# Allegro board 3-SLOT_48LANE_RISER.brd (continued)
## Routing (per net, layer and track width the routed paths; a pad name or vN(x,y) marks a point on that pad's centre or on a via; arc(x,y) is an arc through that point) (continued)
PE_CPU_RX_DN<12>: length 12.1
  TOP w0.135: J5.A69 225.83,5.8 226.17,6.15 226.17,7.46 v2(225.83,7.8)
  IN2 w0.145: v2(225.83,7.8) 226.2,8.16 226.2,9.13 225.61,12.46 225.86,13.88 226.11,14.09 226.15,14.29 J1.A69
PE_CPU_RX_DN<13>: length 12.1
  TOP w0.135: v2(221.82,7.8) 222.17,7.45 222.17,6.15 221.83,5.8 J5.A73
  IN2 w0.145: J1.A73 222.15,14.29 222.11,14.09 221.86,13.88 221.61,12.46 222.2,9.13 222.2,8.17 221.83,7.8 v2(221.82,7.8)
PE_CPU_RX_DN<14>: length 12.1
  TOP w0.135: J5.A77 217.83,5.8 218.17,6.15 218.17,7.43 v2(217.81,7.8)
  IN2 w0.145: v2(217.81,7.8) 217.83,7.8 218.2,8.17 218.2,9.13 217.61,12.46 217.86,13.88 218.11,14.09 218.15,14.29 J1.A77
PE_CPU_RX_DN<15>: length 12.2
  TOP w0.135: J5.A81 213.83,5.52 214.2,5.89 214.2,6.26 214.45,7.28 214.45,7.43 v2(214.07,7.82)
  IN2 w0.145: v2(214.07,7.82) 214.13,7.83 214.42,8.24 213.64,12.64 213.86,13.88 214.11,14.09 214.15,14.29 J1.A81
PE_CPU_RX_DP<0>: length 12.2
  TOP w0.135: v2(278.84,7.8) 278.48,7.44 278.48,6.15 278.83,5.8 J5.A16
  IN2 w0.145: v2(278.84,7.8) 278.47,8.17 278.47,9.16 278.34,9.9 278.44,10.05 278.35,10.57 278.21,10.67 278.13,11.12 278.23,11.26 278.14,11.78 277.99,11.88 277.89,12.46 278.12,13.73 278.26,13.85 278.39,13.81 J1.A16
PE_CPU_RX_DP<1>: length 12.2
  TOP w0.135: v2(273.84,7.8) 273.48,7.44 273.48,6.15 273.83,5.8 J5.A21
  IN2 w0.145: v2(273.84,7.8) 273.46,8.18 274.13,11.99 273.97,12.92 273.97,12.94 273.96,12.95 273.8,13.86 273.61,14 273.58,14.01 273.54,14.03 273.48,14.24 J1.A21
PE_CPU_RX_DP<2>: length 12.2
  TOP w0.135: J5.A25 269.83,5.8 269.48,6.15 269.48,7.43 v2(269.85,7.8)
  IN2 w0.145: J1.A25 269.48,14.24 269.54,14.03 269.58,14.01 269.61,14 269.8,13.86 269.96,12.95 269.97,12.94 269.97,12.92 270.13,11.99 269.46,8.18 269.84,7.8 v2(269.85,7.8)
PE_CPU_RX_DP<3>: length 12.2
  TOP w0.135: v2(265.84,7.8) 265.48,7.44 265.48,6.15 265.83,5.81 J5.A29
  IN2 w0.145: J1.A29 265.48,14.24 265.54,14.03 265.58,14.01 265.61,14 265.8,13.86 265.96,12.95 265.97,12.94 265.97,12.92 266.13,11.99 265.46,8.18 v2(265.84,7.8)
PE_CPU_RX_DP<4>: length 12.2
  TOP w0.135: v2(259.84,7.8) 259.48,7.44 259.48,6.15 259.83,5.8 J5.A35
  IN2 w0.145: J1.A35 259.48,14.24 259.54,14.03 259.58,14.01 259.61,14 259.8,13.86 259.96,12.95 259.97,12.94 259.97,12.92 260.13,11.99 259.47,8.26 259.47,8.17 v2(259.84,7.8)
PE_CPU_RX_DP<5>: length 12.2
  TOP w0.135: v2(255.83,7.8) 255.48,7.45 255.48,6.15 255.83,5.8 J5.A39
  IN2 w0.145: v2(255.83,7.8) 255.46,8.17 255.46,8.18 256.13,11.99 255.97,12.92 255.97,12.94 255.96,12.95 255.8,13.86 255.61,14 255.58,14.01 255.54,14.03 255.48,14.24 J1.A39
PE_CPU_RX_DP<6>: length 12.2
  TOP w0.135: v2(251.84,7.8) 251.48,7.44 251.48,6.15 251.83,5.8 J5.A43
  IN2 w0.145: J1.A43 251.48,14.24 251.54,14.03 251.58,14.01 251.61,14 251.8,13.86 251.96,12.95 251.97,12.94 251.97,12.92 252.13,11.99 251.46,8.18 251.84,7.8 v2(251.84,7.8)
PE_CPU_RX_DP<7>: length 12.2
  TOP w0.135: v2(247.83,7.8) 247.48,7.45 247.48,6.15 247.83,5.8 J5.A47
  IN2 w0.145: v2(247.83,7.8) 247.47,8.16 247.47,8.26 248.13,11.99 247.97,12.92 247.97,12.94 247.96,12.95 247.8,13.86 247.61,14 247.58,14.01 247.54,14.03 247.48,14.24 J1.A47
PE_CPU_RX_DP<8>: length 12.2
  TOP w0.135: J5.A52 242.83,5.8 242.48,6.15 242.48,7.43 v2(242.85,7.8)
  IN2 w0.145: v2(242.85,7.8) 242.47,8.18 242.47,9.16 242.34,9.9 242.44,10.05 242.35,10.57 242.21,10.67 242.13,11.12 242.23,11.26 242.14,11.78 241.99,11.88 241.89,12.46 242.12,13.73 242.26,13.85 242.39,13.81 J1.A52
PE_CPU_RX_DP<9>: length 12.2
  TOP w0.135: v2(238.84,7.8) 238.48,7.44 238.48,6.15 238.83,5.8 J5.A56
  IN2 w0.145: J1.A56 238.39,13.81 238.26,13.85 238.12,13.73 237.89,12.46 237.99,11.88 238.14,11.78 238.23,11.26 238.13,11.12 238.21,10.67 238.35,10.57 238.44,10.05 238.34,9.9 238.47,9.16 238.47,8.17 v2(238.84,7.8)
PE_CPU_RX_DP<10>: length 12.2
  TOP w0.135: v2(234.82,7.8) 234.48,7.46 234.48,6.15 234.83,5.8 J5.A60
  IN2 w0.145: J1.A60 234.39,13.81 234.26,13.85 234.12,13.73 233.89,12.46 233.99,11.88 234.14,11.78 234.23,11.26 234.13,11.12 234.21,10.67 234.35,10.57 234.44,10.05 234.34,9.9 234.47,9.16 234.47,8.15 v2(234.82,7.8)
PE_CPU_RX_DP<11>: length 12.2
  TOP w0.135: J5.A64 230.83,5.8 230.48,6.15 230.48,7.44 v2(230.84,7.8)
  IN2 w0.145: v2(230.84,7.8) 230.47,8.16 230.47,9.16 230.34,9.9 230.44,10.05 230.35,10.57 230.21,10.67 230.13,11.12 230.23,11.26 230.14,11.78 229.99,11.88 229.89,12.46 230.12,13.73 230.26,13.85 230.39,13.81 J1.A64
PE_CPU_RX_DP<12>: length 12.2
  TOP w0.135: J5.A68 226.83,5.8 226.48,6.15 226.48,7.43 v2(226.85,7.8)
  IN2 w0.145: J1.A68 226.39,13.81 226.26,13.85 226.12,13.73 225.89,12.46 225.99,11.88 226.14,11.78 226.23,11.26 226.13,11.12 226.21,10.67 226.35,10.57 226.44,10.05 226.34,9.9 226.47,9.16 226.47,8.17 226.84,7.8 v2(226.85,7.8)
PE_CPU_RX_DP<13>: length 12.2
  TOP w0.135: J5.A72 222.83,5.8 222.48,6.15 222.48,7.45 v2(222.84,7.8)
  IN2 w0.145: J1.A72 222.39,13.81 222.26,13.85 222.12,13.73 221.89,12.46 221.99,11.88 222.14,11.78 222.23,11.26 222.13,11.12 222.21,10.67 222.35,10.57 222.44,10.05 222.34,9.9 222.47,9.16 222.47,8.16 v2(222.84,7.8)
PE_CPU_RX_DP<14>: length 12.2
  TOP w0.135: J5.A76 218.83,5.8 218.48,6.15 218.48,7.46 v2(218.82,7.8)
  IN2 w0.145: J1.A76 218.39,13.81 218.26,13.85 218.12,13.73 217.89,12.46 217.99,11.88 218.14,11.78 218.23,11.26 218.13,11.12 218.21,10.67 218.35,10.57 218.44,10.05 218.34,9.9 218.47,9.16 218.47,8.15 v2(218.82,7.8)
PE_CPU_RX_DP<15>: length 12.1
  TOP w0.135: v2(215.08,7.82) 214.76,7.5 214.76,7.24 214.5,6.22 214.5,5.89 214.83,5.57 J5.A80
  IN2 w0.145: J1.A80 214.39,13.81 214.26,13.85 214.12,13.73 213.92,12.64 214.7,8.25 214.77,8.04 v2(215.08,7.82)
PE_CPU_TX_DN<0>: length 16.9
  BOTTOM w0.135: J5.B15 279.83,5.8 280.17,6.15 280.17,6.81 279.93,8.2 279.64,8.61 279.36,9.02 279.2,9.91 279.33,10.64 279.21,10.8 279.3,11.33 279.47,11.44 279.69,12.7 279.69,13.5 280.65,14.47 280.65,15.96 280.5,16.11 280.5,16.52 280.65,16.67 280.65,18.03 280.51,18.17 280.38,18.24 280.2,18.18 J1.B15
PE_CPU_TX_DN<1>: length 16.9
  BOTTOM w0.135: J1.B20 275.2,18.69 275.14,18.52 274.94,18.42 274.67,18.15 274.67,14.43 275.7,13.4 275.7,12.28 275.34,10.22 275.55,9.03 275.17,6.92 275.17,6.15 274.83,5.8 J5.B20
PE_CPU_TX_DN<2>: length 16.9
  BOTTOM w0.135: J1.B24 271.2,18.69 271.14,18.51 271.11,18.49 270.91,18.39 270.67,18.15 270.67,14.35 271.65,13.37 271.65,12.27 271.47,11.2 271.35,10.56 271.59,9.19 271.17,6.8 271.17,6.15 270.83,5.8 J5.B24
PE_CPU_TX_DN<3>: length 16.9
  BOTTOM w0.135: J1.B28 267.2,18.69 267.14,18.52 266.94,18.42 266.67,18.15 266.67,14.43 267.64,13.46 267.64,12.37 267.32,10.56 267.55,9.25 267.17,7.1 267.17,6.15 266.83,5.8 J5.B28
PE_CPU_TX_DN<4>: length 16.9
  BOTTOM w0.135: J1.B34 261.2,18.69 261.14,18.51 260.92,18.4 260.68,18.16 260.68,14.25 261.68,13.25 261.68,12.34 261.52,11.39 261.34,10.37 261.56,9.13 261.17,6.96 261.17,6.15 260.83,5.8 J5.B34
PE_CPU_TX_DN<5>: length 16.8
  BOTTOM w0.135: J5.B38 256.83,5.8 257.17,6.15 257.17,6.8 257.39,8.05 257.4,8.05 257.55,8.94 257.3,10.37 257.49,11.44 257.66,12.39 257.66,13.34 256.7,14.29 256.7,18.18 256.92,18.4 257.14,18.51 257.2,18.69 J1.B38
PE_CPU_TX_DN<6>: length 16.8
  BOTTOM w0.135: J5.B42 252.83,5.8 253.17,6.15 253.17,7.22 253.52,9.2 253.3,10.48 253.64,12.43 253.64,13.4 252.7,14.34 252.7,18.18 252.92,18.4 253.14,18.51 253.2,18.69 J1.B42
PE_CPU_TX_DN<7>: length 16.8
  BOTTOM w0.135: J5.B46 248.83,5.8 249.17,6.15 249.17,7.35 249.52,9.32 249.31,10.52 249.64,12.4 249.64,13.44 248.7,14.38 248.7,18.18 248.92,18.4 249.14,18.51 249.2,18.69 J1.B46
PE_CPU_TX_DN<8>: length 16.8
  BOTTOM w0.135: J5.B51 243.83,5.8 244.17,6.15 244.17,6.95 243.75,9.35 243.98,10.62 243.84,11.36 243.67,11.48 243.6,11.88 243.72,12.06 243.65,12.46 243.65,13.42 244.67,14.43 244.67,16.08 244.51,16.24 244.51,16.64 244.67,16.79 244.67,18.01 244.51,18.17 244.38,18.24 244.2,18.18 J1.B51
PE_CPU_TX_DN<9>: length 16.7
  BOTTOM w0.135: J5.B55 239.83,5.8 240.17,6.15 240.17,7.04 239.8,9.17 240.04,10.51 239.88,11.39 239.7,11.51 239.63,11.91 239.76,12.09 239.69,12.48 239.69,13.59 240.63,14.53 240.63,15.98 240.48,16.14 240.48,16.54 240.63,16.69 240.63,18.05 240.51,18.17 240.38,18.24 240.2,18.18 J1.B55
PE_CPU_TX_DN<10>: length 16.7
  BOTTOM w0.135: J1.B59 236.2,18.18 236.38,18.24 236.51,18.17 236.65,18.03 236.65,16.86 236.5,16.71 236.5,16.3 236.65,16.15 236.65,14.33 235.71,13.39 235.71,12.48 235.79,12.05 235.66,11.88 235.74,11.43 235.92,11.31 236.09,10.35 235.83,8.85 236.17,6.88 236.17,6.15 235.83,5.8 J5.B59
PE_CPU_TX_DN<11>: length 16.7
  BOTTOM w0.135: J1.B63 232.2,18.18 232.38,18.24 232.51,18.17 232.67,18.02 232.67,16.87 232.51,16.72 232.51,16.31 232.67,16.16 232.67,14.61 231.69,13.64 231.69,12.45 231.78,11.97 231.65,11.79 231.72,11.39 231.9,11.27 232.07,10.32 231.85,9.08 232.17,7.22 232.17,6.15 231.83,5.8 J5.B63
PE_CPU_TX_DN<12>: length 16.9
  BOTTOM w0.135: J5.B67 227.83,5.8 228.17,6.15 228.17,7.72 228.05,8.43 227.87,8.56 227.8,8.96 227.93,9.13 227.86,9.53 228.01,10.41 227.86,11.3 227.68,11.42 227.61,11.82 227.73,12 227.69,12.25 227.69,13.61 228.68,14.61 228.68,16.11 228.52,16.26 228.52,16.67 228.68,16.82 228.68,18.03 228.55,18.15 228.38,18.24 228.2,18.18 J1.B67
PE_CPU_TX_DN<13>: length 16.9
  BOTTOM w0.135: J1.B71 224.2,18.18 224.38,18.24 224.51,18.17 224.67,18.01 224.67,16.74 224.52,16.59 224.52,16.19 224.67,16.03 224.67,14.58 223.68,13.59 223.68,12.47 223.75,12.09 223.62,11.91 223.7,11.51 223.87,11.39 224.04,10.41 223.83,9.22 223.9,8.82 223.78,8.65 223.85,8.25 224.03,8.12 224.17,7.29 224.17,6.15 223.83,5.8 J5.B71
PE_CPU_TX_DN<14>: length 16.8
  BOTTOM w0.135: J1.B75 220.2,18.18 220.38,18.24 220.51,18.17 220.68,18 220.68,16.92 220.53,16.77 220.53,16.37 220.68,16.21 220.68,14.45 219.67,13.44 219.67,11.68 219.57,11.53 219.64,11.13 219.81,11 219.93,10.37 219.72,9.24 220.17,6.69 220.17,6.15 219.83,5.8 J5.B75
PE_CPU_TX_DN<15>: length 17
  BOTTOM w0.135: J1.B79 216.2,18.18 216.38,18.24 216.51,18.17 216.69,17.99 216.69,16.9 216.54,16.75 216.54,16.35 216.69,16.19 216.69,14.48 215.67,13.46 215.67,12.24 215.81,11.83 215.72,11.63 215.84,11.25 216.04,11.15 216.32,10.32 216.24,9.9 216.07,9.78 216,9.38 216.12,9.2 216.09,9.02 216.17,8.54 216.17,5.89 215.83,5.54 J5.B79
PE_CPU_TX_DP<0>: length 17
  BOTTOM w0.135: J5.B14 280.83,5.8 280.48,6.15 280.48,6.83 280.22,8.32 279.64,9.14 279.51,9.9 279.99,12.67 279.99,13.38 280.96,14.34 280.96,18.15 280.69,18.43 280.52,18.51 280.46,18.69 J1.B14
PE_CPU_TX_DP<1>: length 16.9
  BOTTOM w0.135: J1.B19 275.46,18.18 275.27,18.24 275.12,18.17 274.98,18.03 274.98,16.74 275.13,16.58 275.13,16.18 274.98,16.03 274.98,14.56 276.01,13.53 276.01,12.25 275.92,11.74 276.04,11.57 275.97,11.17 275.79,11.05 275.65,10.22 275.86,9.03 275.77,8.56 275.9,8.39 275.83,7.99 275.65,7.86 275.48,6.89 275.48,6.15 275.83,5.8 J5.B19
PE_CPU_TX_DP<2>: length 16.8
  BOTTOM w0.135: J5.B23 271.83,5.8 271.48,6.15 271.48,6.78 271.9,9.19 271.66,10.56 271.77,11.14 271.94,11.27 272.01,11.67 271.89,11.84 271.96,12.24 271.96,13.49 270.98,14.47 270.98,16.03 271.13,16.18 271.13,16.58 270.98,16.74 270.98,18.03 271.09,18.14 271.28,18.24 271.46,18.18 J1.B23
PE_CPU_TX_DP<3>: length 16.9
  BOTTOM w0.135: J5.B27 267.83,5.8 267.48,6.15 267.48,7.07 267.67,8.15 267.85,8.27 267.92,8.67 267.79,8.85 267.86,9.25 267.63,10.56 267.75,11.25 267.93,11.37 268,11.77 267.88,11.95 267.95,12.34 267.95,13.59 266.98,14.56 266.98,16.03 267.13,16.18 267.13,16.58 266.98,16.74 266.98,18.03 267.12,18.17 267.27,18.24 267.46,18.18 J1.B27
PE_CPU_TX_DP<4>: length 16.9
  BOTTOM w0.135: J5.B33 261.83,5.8 261.48,6.15 261.48,6.94 261.67,8.03 261.85,8.15 261.92,8.55 261.8,8.73 261.87,9.13 261.65,10.37 261.79,11.21 261.97,11.34 262.04,11.73 261.92,11.91 261.99,12.31 261.99,13.38 260.98,14.38 260.98,16.05 261.14,16.21 261.14,16.61 260.98,16.76 260.98,18.03 261.11,18.15 261.28,18.24 261.46,18.18 J1.B33
PE_CPU_TX_DP<5>: length 16.7
  BOTTOM w0.135: J5.B37 257.83,5.8 257.48,6.15 257.48,6.77 257.67,7.84 257.67,7.84 257.86,8.94 257.61,10.37 257.77,11.26 257.95,11.39 258.02,11.78 257.89,11.96 257.96,12.36 257.96,13.46 257.01,14.42 257.01,16 257.16,16.15 257.16,16.55 257.01,16.71 257.01,18.06 257.11,18.15 257.28,18.24 257.46,18.18 J1.B37
PE_CPU_TX_DP<6>: length 16.9
  BOTTOM w0.135: J5.B41 253.83,5.8 253.48,6.15 253.48,7.19 253.64,8.11 253.82,8.23 253.89,8.63 253.76,8.8 253.83,9.2 253.61,10.48 253.76,11.31 253.93,11.43 254,11.83 253.88,12 253.95,12.4 253.95,13.53 253.01,14.47 253.01,16 253.16,16.15 253.16,16.55 253.01,16.71 253.01,18.06 253.11,18.15 253.28,18.24 253.46,18.18 J1.B41
PE_CPU_TX_DP<7>: length 16.9
  BOTTOM w0.135: J1.B45 249.46,18.18 249.28,18.24 249.11,18.15 249.01,18.06 249.01,16.71 249.16,16.55 249.16,16.15 249.01,16 249.01,14.51 249.95,13.57 249.95,12.38 249.88,11.98 250,11.8 249.93,11.4 249.75,11.28 249.62,10.52 249.83,9.32 249.76,8.92 249.89,8.75 249.82,8.35 249.64,8.23 249.48,7.32 249.48,6.15 249.83,5.8 J5.B45
PE_CPU_TX_DP<8>: length 16.9
  BOTTOM w0.135: J5.B50 244.83,5.8 244.48,6.15 244.48,6.98 244.06,9.35 244.28,10.62 243.96,12.48 243.96,13.29 244.97,14.31 244.97,18.14 244.69,18.43 244.52,18.51 244.46,18.69 J1.B50
PE_CPU_TX_DP<9>: length 16.8
  BOTTOM w0.135: J1.B54 240.46,18.69 240.52,18.51 240.69,18.43 240.93,18.18 240.93,14.41 239.99,13.47 239.99,12.51 240.35,10.51 240.11,9.17 240.48,7.06 240.48,6.15 240.83,5.8 J5.B54
PE_CPU_TX_DP<10>: length 16.8
  BOTTOM w0.135: J1.B58 236.46,18.69 236.52,18.51 236.52,18.51 236.69,18.43 236.96,18.15 236.96,14.2 236.02,13.26 236.02,12.51 236.15,11.76 236.21,11.41 236.4,10.35 236.14,8.85 236.48,6.91 236.48,6.15 236.83,5.8 J5.B58
PE_CPU_TX_DP<11>: length 16.8
  BOTTOM w0.135: J5.B62 232.83,5.8 232.48,6.15 232.48,7.25 232.16,9.08 232.38,10.32 232.2,11.32 232.2,11.32 232.2,11.32 232,12.48 232,13.51 232.97,14.48 232.97,18.14 232.69,18.43 232.52,18.51 232.52,18.51 232.46,18.69 J1.B62
PE_CPU_TX_DP<12>: length 16.9
  BOTTOM w0.135: J1.B66 228.46,18.69 228.52,18.51 228.73,18.4 228.98,18.15 228.98,14.48 227.99,13.49 227.99,12.28 228.32,10.42 228.16,9.53 228.47,7.77 228.48,7.77 228.48,6.15 228.83,5.8 J5.B66
PE_CPU_TX_DP<13>: length 16.9
  BOTTOM w0.135: J1.B70 224.46,18.69 224.52,18.51 224.69,18.43 224.98,18.13 224.98,14.46 223.99,13.47 223.99,12.5 224.35,10.41 224.14,9.22 224.48,7.32 224.48,6.15 224.83,5.8 J5.B70
PE_CPU_TX_DP<14>: length 16.9
  BOTTOM w0.135: J5.B74 220.83,5.8 220.48,6.15 220.48,6.72 220.03,9.24 220.23,10.37 219.98,11.84 219.98,13.31 220.98,14.32 220.98,18.13 220.69,18.43 220.52,18.51 220.46,18.69 J1.B74
PE_CPU_TX_DP<15>: length 16.9
  BOTTOM w0.135: J1.B78 216.46,18.69 216.52,18.51 216.69,18.43 216.99,18.12 216.99,14.35 215.98,13.34 215.98,12.29 216.63,10.34 216.4,9.02 216.48,8.56 216.48,5.9 216.83,5.55 J5.B78
PE_SLOT2_PRES_N: length 166.6
  TOP w0.114: R44.2 59.89,63.6 61.14,62.36 92.46,62.36 v2(101.07,53.75) ; J2.B81 213.83,37.94 212.79,38.97 212.5,38.97 209.91,41.57 209.91,41.74 209.79,41.86 168.28,41.86 v2(158.73,51.41)
  IN2 w0.147: v2(101.07,53.75) 103.18,55.85 153.83,55.85 158.28,51.41 v2(158.73,51.41)
PE_SLOT2_RX_DN<0>: length 229.5
  IN2 w0.089: 74.39,75.64 74.37,75.64 74.33,75.68 73.54,75.68 73.12,75.27 73.12,75.19 73.12,75.12 72.85,74.84 72.77,74.84 72.7,74.84 72.4,74.55 72.01,74.55 71.93,74.47 71.48,74.47 71.4,74.55 69.84,74.55 v3(69.65,74.36)
  IN2 w0.145: J2.A17 278.2,34.51 278.4,34.44 278.54,34.52 278.69,34.67 278.69,38.11 277.65,39.15 277.65,40.65 277.34,41.09 277.34,41.09 276.05,42.93 275.75,44.63 274.73,46.09 272.3,47.79 272.1,47.76 271.54,48.16 271.5,48.35 271.03,48.68 270.87,48.65 270.26,49.08 270.23,49.24 269.76,49.57 269.54,49.53 269,49.91 268.96,50.13 255.75,59.38 184.1,72.01 180.82,74.31 137.84,81.89 96.66,74.63 95.12,74.9 94.98,74.8 94.48,74.89 94.38,75.03 93.94,75.11 93.8,75.01 93.29,75.1 93.2,75.24 92.75,75.31 92.61,75.22 92.11,75.31 92.01,75.44 90.72,75.67 89.74,75.5 89.65,75.38 89.11,75.28 88.99,75.37 88.55,75.29 88.46,75.17 87.92,75.07 87.8,75.16 86.95,75.01 85.91,75.01 85.78,74.88 85.3,74.88 85.17,75.01 84.72,75.01 84.59,74.88 84.11,74.88 83.98,75.01 82.97,75.01 82.17,75.15 82.02,75.04 81.54,75.13 81.44,75.28 81,75.35 80.85,75.25 80.37,75.34 80.27,75.48 79.39,75.64 76.84,75.64 76.71,75.51 76.23,75.51 76.1,75.64 75.65,75.64 75.52,75.51 75.04,75.51 74.91,75.64 74.39,75.64
  BOTTOM w0.135: U1.D11 v3(69.65,74.36)
PE_SLOT2_RX_DN<1>: length 228.4
  IN2 w0.089: v3(69.65,73.56) 69.84,73.75 69.98,73.75 70.18,73.95 70.89,73.95 71.17,73.67 74.38,73.67 74.43,73.63 74.45,73.63
  IN2 w0.145: 74.45,73.63 74.8,73.63 75.14,73.69 75.53,73.85 75.69,73.78 76.18,73.99 76.24,74.15 76.66,74.32 76.82,74.25 77.31,74.46 77.37,74.62 77.62,74.72 78.05,74.79 79.96,74.46 80.12,74.24 80.09,74.08 80.38,73.67 80.87,73.58 81.28,73.87 81.31,74.02 81.53,74.18 82.98,73.92 84.15,73.92 84.26,73.81 84.89,73.81 85,73.92 85.45,73.92 85.56,73.81 86.19,73.81 86.3,73.92 87.3,73.92 90.63,74.51 96.77,73.43 118.26,77.22 118.27,77.22 137.86,80.67 180.43,73.17 183.78,70.83 254.02,58.45 260.51,53.91 260.54,53.7 261.09,53.32 261.29,53.36 261.77,53.02 261.8,52.83 262.35,52.44 262.55,52.48 263.02,52.14 263.05,51.98 263.64,51.57 263.81,51.6 264.28,51.26 264.31,51.08 264.89,50.68 265.06,50.71 267.79,48.81 267.84,48.54 267.22,47.66 267.31,47.17 267.72,46.88 268.21,46.97 268.83,47.85 269.09,47.89 270.38,47 271.83,44.92 272.33,42.08 273.69,40.14 273.69,39.33 272.69,38.33 272.69,34.55 272.95,34.29 273.14,34.2 273.15,34.18 273.21,34.02 J2.A22
  BOTTOM w0.135: U1.D10 v3(69.65,73.56)
PE_SLOT2_RX_DN<2>: length 220.5
  IN2 w0.089: v3(69.65,71.96) 69.84,72.15 74.38,72.15 74.43,72.1 74.45,72.1
  IN2 w0.145: J2.A26 269.21,34.02 269.15,34.18 269.14,34.2 268.95,34.29 268.69,34.55 268.69,38.27 269.67,39.26 269.67,40.67 267.71,43.47 267.44,45 266.92,45.74 266.74,45.77 266.33,46.37 266.36,46.54 266.02,47.02 265.88,47.04 265.44,47.67 265.46,47.82 264.93,48.58 251.99,57.64 183.47,69.72 179.91,72.21 137.99,79.6 96.6,72.3 90.85,73.32 87.15,72.67 86.31,72.67 86.18,72.54 85.69,72.54 85.56,72.67 85.11,72.67 84.98,72.54 84.49,72.54 84.36,72.67 83.91,72.67 83.78,72.54 83.3,72.54 83.17,72.67 82.72,72.67 82.59,72.54 82.1,72.54 81.97,72.67 81.52,72.67 81.39,72.54 80.9,72.54 80.77,72.67 80.32,72.67 80.19,72.54 79.7,72.54 79.58,72.67 78.13,72.67 74.94,72.1 74.45,72.1
  BOTTOM w0.135: U1.D8 v3(69.65,71.96)
PE_SLOT2_RX_DN<3>: length 220.1
  IN2 w0.089: v3(69.65,71.16) 69.84,71.35 69.98,71.35 70.18,71.55 71.96,71.55 73.88,71.21 74.38,71.21 74.43,71.17 74.45,71.17
  IN2 w0.145: 74.45,71.17 75.3,71.17 78.28,71.69 78.87,71.69 78.99,71.57 79.58,71.57 79.7,71.69 80.15,71.69 80.27,71.57 80.86,71.57 80.98,71.69 81.43,71.69 81.55,71.57 82.14,71.57 82.27,71.69 83.87,71.69 84,71.56 84.57,71.56 84.7,71.69 85.15,71.69 85.28,71.56 85.86,71.56 85.98,71.69 87.61,71.69 90.96,72.28 92.58,72 92.65,71.89 93.22,71.79 93.32,71.87 93.76,71.79 93.83,71.69 94.4,71.59 94.5,71.66 96.52,71.3 137.7,78.56 179.08,71.27 182.83,68.64 240.86,58.42 250.66,56.69 255.02,53.63 255.07,53.38 255.45,53.11 255.7,53.16 256.09,52.89 256.14,52.63 256.52,52.36 256.77,52.41 258.65,51.09 259.2,50.31 259.15,50.04 258.26,49.42 258.17,48.93 258.46,48.51 258.96,48.43 259.85,49.05 260.11,49 260.27,48.78 260.22,48.52 259.69,48.14 259.61,47.71 259.96,47.23 260.39,47.15 260.92,47.52 261.18,47.48 262.56,45.51 262.56,45.5 263.15,42.2 263.44,41.78 263.7,40.31 263.7,39.13 264.69,38.15 264.69,34.55 264.95,34.29 265.14,34.2 265.15,34.18 265.21,34.02 J2.A30
  BOTTOM w0.135: U1.D7 v3(69.65,71.16)
PE_SLOT2_RX_DN<4>: length 211
  IN2 w0.089: v3(69.65,69.56) 69.84,69.75 72.04,69.75 72.87,69.89 74.04,69.89 74.08,69.85 74.1,69.85
  IN2 w0.145: J2.A36 259.21,34.02 259.15,34.18 259.14,34.2 258.95,34.29 258.69,34.55 258.69,38.35 259.69,39.36 259.69,40.31 259.61,40.77 258.43,42.46 258.19,42.7 257.61,43.52 257.23,45.7 256.09,47.31 255.9,47.35 255.59,47.79 255.62,47.98 255.34,48.38 255.17,48.41 254.84,48.88 254.87,49.05 254.6,49.45 254.44,49.48 254.1,49.97 254.13,50.12 253.85,50.52 253.67,50.55 253.35,51.02 253.38,51.19 252.08,53.04 247.9,55.97 236.18,58.03 182.4,67.52 178.49,70.25 137.66,77.45 95.84,70.08 90.46,71.03 87.19,70.45 82.78,70.45 82.69,70.36 82.11,70.36 82.02,70.45 81.57,70.45 81.48,70.36 80.9,70.36 80.81,70.45 80.37,70.45 80.27,70.36 79.7,70.36 79.61,70.45 78.07,70.45 77.33,70.32 77.24,70.19 76.66,70.09 76.53,70.18 76.08,70.1 75.99,69.97 75.41,69.86 75.28,69.96 74.68,69.85 74.1,69.85
  BOTTOM w0.135: U1.D5 v3(69.65,69.56)
PE_SLOT2_RX_DN<5>: length 209.2
  IN2 w0.089: 73.84,68.83 73.82,68.83 73.77,68.87 73.3,68.87 73.02,69.15 72.66,69.15 72.6,69.09 72.08,69.09 72.01,69.15 71.62,69.15 71.56,69.09 71.04,69.09 70.97,69.15 70.18,69.15 69.98,68.95 69.84,68.95 v3(69.65,68.76)
  IN2 w0.145: 73.84,68.83 74.99,68.83 75.77,68.97 75.91,68.87 76.49,68.97 76.59,69.11 77.03,69.19 77.17,69.09 77.76,69.2 77.85,69.33 78.26,69.41 87.77,69.41 87.9,69.28 88.6,69.28 88.73,69.41 89.73,69.41 90.09,69.66 90.13,69.9 90.35,70.06 90.62,70.01 90.78,69.79 90.73,69.54 91.02,69.13 91.52,69.04 91.93,69.33 91.97,69.58 92.19,69.73 92.46,69.68 92.61,69.46 92.57,69.21 92.86,68.8 93.49,68.69 93.49,68.69 137.24,76.4 177.86,69.24 181.77,66.5 245.04,55.35 245.98,54.69 246.02,54.48 246.43,54.19 246.64,54.23 247.05,53.94 247.09,53.74 247.5,53.45 247.71,53.48 249.54,52.2 251.07,50.01 251.05,49.85 251.38,49.37 251.54,49.35 251.99,48.7 251.96,48.54 252.28,48.08 252.45,48.05 253,47.26 253.76,42.95 254.83,41.41 255.59,40.62 255.68,40.12 255.68,39.36 254.69,38.37 254.69,34.55 254.95,34.29 255.14,34.2 255.15,34.18 255.21,34.02 J2.A40
  BOTTOM w0.135: U1.D4 v3(69.65,68.76)
PE_SLOT2_RX_DN<6>: length 202.6
  IN2 w0.089: v3(69.65,67.16) 69.84,67.35 69.98,67.35 70.18,67.55 70.89,67.55 71.17,67.27 72.22,67.27 72.26,67.23 72.29,67.23
  IN2 w0.145: J2.A44 251.21,34.02 251.15,34.18 251.14,34.2 250.95,34.29 250.69,34.55 250.69,38.33 251.66,39.31 251.66,39.95 251.55,40.58 251.02,41.34 250.05,42.73 249.6,45.31 249.17,45.92 249.04,45.94 248.68,46.45 248.7,46.59 248.42,46.99 248.27,47.01 247.92,47.5 247.95,47.66 247.67,48.06 247.5,48.09 247.17,48.56 247.2,48.73 246.92,49.13 246.76,49.15 246.43,49.64 246.45,49.8 245.78,50.76 245.64,50.78 245.34,51.22 245.36,51.36 244.94,51.95 240.69,54.93 228.55,57.07 181.41,65.38 177.38,68.21 136.97,75.33 93.29,67.63 92.21,67.83 92.07,67.73 91.53,67.82 91.43,67.96 90.99,68.04 90.85,67.94 90.3,68.04 90.21,68.18 89.43,68.32 85.08,68.32 84.96,68.2 84.36,68.2 84.24,68.32 80.59,68.32 80.46,68.19 79.97,68.19 79.84,68.32 78.76,68.32 74.45,67.56 72.59,67.23 72.29,67.23
  BOTTOM w0.135: U1.D2 v3(69.65,67.16)
PE_SLOT2_RX_DN<7>: length 200.6
  IN2 w0.089: 71.93,66.5 71.91,66.5 71.86,66.55 71.07,66.55 70.98,66.46 70.54,66.46 70.46,66.55 69.84,66.55 v3(69.65,66.36)
  IN2 w0.145: J2.A48 247.21,34.02 247.15,34.18 247.14,34.2 246.95,34.29 246.69,34.55 246.69,38.11 245.7,39.1 245.7,40.92 245.62,41.34 245.05,42.15 244.87,42.19 244.59,42.59 244.62,42.77 244.36,43.14 244.18,43.17 243.9,43.58 243.93,43.76 243.25,44.73 242.93,46.54 242.86,46.59 242.74,47.27 242.79,47.34 242.7,47.83 242.59,47.91 242.48,48.51 242.56,48.62 242.47,49.11 242.35,49.2 242.25,49.79 242.33,49.91 242.15,50.94 241.53,51.83 240.04,52.87 239.94,52.85 239.3,53.3 239.29,53.4 238,54.3 237.08,54.46 237.02,54.42 235.9,54.61 235.86,54.67 181,64.35 177.26,66.96 136.72,74.11 90.31,65.93 89.32,66.1 89.03,66.51 89.13,67.04 88.97,67.26 88.7,67.3 88.48,67.15 88.39,66.63 87.98,66.34 86.64,66.58 86.35,66.99 86.4,67.25 86.28,67.42 85.93,67.48 85.76,67.36 85.71,67.1 85.3,66.81 84.46,66.96 84.28,66.83 83.83,66.91 83.71,67.09 82.83,67.25 81.6,67.25 81.36,67 80.47,67 80.22,67.25 79.65,67.25 79.4,67 78.52,67 78.27,67.25 77.68,67.25 75.79,66.91 75.67,66.75 75.2,66.66 75.04,66.77 73.58,66.51 73.56,66.5 71.93,66.5
  BOTTOM w0.135: U1.D1 v3(69.65,66.36)
PE_SLOT2_RX_DN<8>: length 197.3
  IN2 w0.089: v3(66.45,68.76) 66.64,68.58 66.64,67.08 66.59,67.04 66.54,66.99 66.54,66.6 66.59,66.55 66.64,66.5 66.64,65.95 66.59,65.91 66.59,65.89
  IN2 w0.145: 66.59,65.89 66.59,65.42 66.99,65.02 70.81,65.02 71.42,65.63 74.21,65.63 74.45,65.68 76.16,65.98 76.84,65.98 76.98,65.85 77.48,65.85 77.61,65.98 78.06,65.98 78.19,65.85 78.7,65.85 78.83,65.98 79.28,65.98 79.41,65.85 79.92,65.85 80.05,65.98 80.5,65.98 80.63,65.85 81.14,65.85 81.27,65.98 83.32,65.98 83.92,65.87 84.02,65.73 84.55,65.64 84.7,65.74 85.14,65.66 85.24,65.51 85.77,65.42 85.91,65.52 86.36,65.44 86.46,65.3 86.99,65.21 87.13,65.31 90.24,64.76 136.7,72.95 176.99,65.85 180.69,63.25 225.22,55.4 237.56,46.76 239.16,44.47 239.13,44.3 239.42,43.89 239.59,43.86 239.85,43.49 239.82,43.32 240.11,42.91 240.28,42.88 241.69,40.87 241.69,39.25 242.67,38.26 242.67,34.65 242.54,34.52 242.4,34.44 242.2,34.51 J2.A53
  BOTTOM w0.135: U1.H4 v3(66.45,68.76)
PE_SLOT2_RX_DN<9>: length 196
  IN2 w0.089: 65.64,67.08 65.66,67.1 65.72,67.1 66.08,67.46 66.08,68.13 65.84,68.38 65.84,68.58 v3(65.65,68.76)
  IN2 w0.145: J2.A57 238.2,34.51 238.4,34.44 238.54,34.52 238.69,34.67 238.69,38.26 237.71,39.24 237.71,40.47 236.57,42.23 236.4,42.26 236.11,42.7 236.15,42.87 235.9,43.25 235.74,43.28 235.45,43.72 235.49,43.89 235.17,44.38 233.46,46.82 231.04,49.24 223.35,54.63 179.95,62.28 176.18,64.92 136.42,71.93 89.77,63.71 88.77,63.88 88.63,63.78 88.13,63.87 88.04,64.01 87.59,64.09 87.45,63.99 86.95,64.08 86.85,64.22 86.41,64.3 86.27,64.2 85.77,64.29 85.67,64.43 85.23,64.51 85.09,64.41 84.59,64.5 84.49,64.64 83.18,64.87 82.67,64.87 82.55,64.75 81.97,64.75 81.86,64.87 81.34,64.87 81.02,64.54 80.17,64.54 79.84,64.87 79.23,64.87 78.9,64.54 78.06,64.54 77.73,64.87 77.12,64.87 76.79,64.54 75.94,64.54 75.62,64.87 74.87,64.87 74.73,64.73 74.2,64.73 74.05,64.87 72.84,64.87 72.2,64.24 66.51,64.24 66.17,64.58 66.02,64.58 65.62,64.98 65.62,65.13 65.32,65.43 65.32,65.72 65.22,65.83 65.22,66.39 65.32,66.5 65.32,66.76 65.64,67.08
  BOTTOM w0.135: U1.J4 v3(65.65,68.76)
PE_SLOT2_RX_DN<10>: length 194.2
  IN2 w0.089: 63.62,65.84 63.62,65.86 63.66,65.91 63.66,66.65 64.24,67.23 64.24,68.58 v3(64.05,68.76)
  IN2 w0.145: 63.62,65.84 63.62,64.88 63.98,64.52 63.98,64.32 64.34,63.96 64.54,63.96 65.03,63.47 73.54,63.47 74.1,62.92 75.31,62.92 75.86,63.47 76.62,63.47 77.17,62.92 78.09,62.92 78.56,63.39 79.44,63.39 79.56,63.26 80.06,63.26 80.19,63.39 80.64,63.39 80.76,63.26 81.26,63.26 81.39,63.39 82.13,63.39 82.24,63.27 82.79,63.27 82.91,63.39 84.56,63.39 85.45,63.11 85.54,62.94 86.01,62.79 86.17,62.88 86.6,62.74 86.69,62.58 87.15,62.43 87.32,62.52 88.07,62.28 136.49,70.82 175.8,63.89 179.24,61.48 221.13,54.09 224.96,51.41 225,51.2 225.37,50.94 225.58,50.98 225.94,50.72 225.98,50.51 226.35,50.25 226.56,50.29 227.6,49.56 230.48,45.45 230.48,45.45 231.16,44.47 231.13,44.31 231.43,43.89 231.59,43.86 233.61,40.97 233.73,40.29 233.73,39.25 234.7,38.29 234.7,34.68 234.54,34.52 234.4,34.44 234.2,34.51 J2.A61
  BOTTOM w0.135: U1.L4 v3(64.05,68.76)
PE_SLOT2_RX_DN<11>: length 193.1
  IN2 w0.089: v3(63.25,68.76) 63.44,68.58 63.44,68.38 63.72,68.1 63.72,67.8 62.84,66.92 62.84,66.01 62.79,65.96 62.79,65.94
  IN2 w0.145: 62.79,65.94 62.79,64.02 63.55,63.26 63.55,63 63.85,62.71 63.85,62.52 64.21,62.16 64.39,62.16 64.71,61.85 64.71,61.66 65.07,61.3 65.25,61.3 65.72,60.83 66.9,60.83 67.04,60.69 67.54,60.69 67.68,60.83 69.59,60.83 69.72,60.7 70.2,60.7 70.33,60.83 70.78,60.83 70.91,60.7 71.39,60.7 71.52,60.83 74.61,60.83 74.74,60.7 75.23,60.7 75.36,60.83 75.81,60.83 75.94,60.7 76.43,60.7 76.56,60.83 77.41,60.83 77.81,61.24 78.43,61.24 78.83,60.83 79.88,60.83 80.38,60.92 80.58,61.21 81.23,61.32 81.52,61.12 82.31,61.26 82.51,61.55 83.15,61.67 83.44,61.46 84.28,61.61 85.8,61.34 85.81,61.34 86.86,61.15 133.85,69.44 134.01,69.32 134.51,69.41 134.62,69.57 136.27,69.87 175.44,62.97 178.83,60.6 219.43,53.44 222.19,51.68 225.62,46.79 225.59,46.63 225.9,46.19 226.06,46.16 226.32,45.79 226.29,45.63 226.6,45.18 226.76,45.16 229.47,41.29 229.69,40.04 229.69,39.23 230.68,38.24 230.68,34.66 230.54,34.52 230.4,34.44 230.2,34.51 J2.A65
  BOTTOM w0.135: U1.M4 v3(63.25,68.76)
PE_SLOT2_RX_DN<12>: length 191.8
  IN2 w0.089: 61.23,66.43 61.23,66.45 61.28,66.5 61.28,67 61.04,67.24 61.04,68.58 v3(60.85,68.76)
  IN2 w0.145: 61.23,66.43 61.23,65.96 61.14,65.86 61.04,65.76 61.04,65.31 61.14,65.21 61.23,65.11 61.23,64.56 61.84,63.96 61.84,62.3 62.51,61.63 62.51,61.45 62.89,61.07 63.07,61.07 64.47,59.67 64.47,59.5 64.85,59.12 65.03,59.12 65.49,58.65 76.51,58.65 77.41,58.81 78.16,59.33 84.19,60.4 86.37,60.01 136.27,68.8 155.78,65.36 175.28,61.92 178.73,59.51 209.23,54.13 209.32,54 209.81,53.91 209.94,54.01 210.34,53.94 210.43,53.81 210.92,53.72 211.05,53.81 211.87,53.67 212.7,53.52 212.79,53.39 213.29,53.3 213.42,53.39 213.81,53.32 213.9,53.19 214.39,53.11 214.53,53.2 215.35,53.05 218.17,52.56 220.01,51.27 221.41,49.26 221.38,49.12 221.71,48.65 221.86,48.63 222.42,47.83 222.39,47.66 222.66,47.28 222.82,47.25 223.05,46.92 223.02,46.76 223.29,46.37 223.46,46.34 224.01,45.55 224.17,44.62 224.11,44.53 224.24,43.79 224.33,43.72 224.5,42.75 225.54,41.27 225.69,40.42 225.69,39.23 226.68,38.24 226.68,34.66 226.54,34.52 226.4,34.44 226.2,34.51 J2.A69
  BOTTOM w0.135: U1.P4 v3(60.85,68.76)
PE_SLOT2_RX_DN<13>: length 189.7
  IN2 w0.089: v3(60.05,68.76) 60.24,68.58 60.24,66.8 60.19,66.76 60.19,66.73
  IN2 w0.145: J2.A73 222.2,34.51 222.4,34.44 222.54,34.52 222.68,34.66 222.68,38.06 222.53,38.35 222.08,38.73 221.78,39.03 221.69,39.52 221.69,40.23 221.43,41.68 220.4,43.16 220.16,44.51 220.05,44.59 219.92,45.31 220,45.42 219.9,45.99 219.82,46.05 219.68,46.82 219.74,46.9 219.46,48.48 217.66,51.06 217,51.51 215.22,51.83 215.09,51.74 214.6,51.82 214.51,51.95 214.11,52.02 213.98,51.93 213.49,52.02 213.4,52.15 211.82,52.43 205.03,53.62 204.21,53.77 204.08,53.68 203.59,53.76 203.5,53.9 203.1,53.96 202.97,53.87 202.48,53.96 202.39,54.09 201.56,54.24 178.21,58.36 174.35,61.05 137.13,67.62 136.68,67.7 86.06,58.77 83.73,59.18 83.15,59.08 83.05,58.94 82.55,58.85 82.41,58.95 81.35,58.76 81.26,58.63 80.7,58.53 80.59,58.61 78.5,58.24 77.74,57.93 76.77,57.76 64.99,57.76 62.66,60.08 62.49,60.08 62.11,60.46 62.11,60.64 60.19,62.55 60.19,63.52 60.04,63.67 60.04,64.2 60.19,64.35 60.19,64.79 60.06,64.93 60.06,65.46 60.19,65.59 60.19,66.73
  BOTTOM w0.135: U1.R4 v3(60.05,68.76)
PE_SLOT2_RX_DN<14>: length 188.4
  IN2 w0.089: 58.52,66.56 58.52,66.59 58.56,66.62 58.56,66.83 57.86,67.53 57.86,68.2 58.08,68.42 58.08,68.99 v3(58.45,69.56)
  IN2 w0.145: 58.52,66.56 58.52,62.34 63.99,56.87 72.46,56.87 72.9,56.43 73.51,56.43 73.95,56.87 79.09,56.87 79.54,57.32 79.9,57.32 80.36,56.87 81.23,56.87 84.46,57.44 84.69,57.78 85.12,57.85 85.56,57.54 135.07,66.32 135.22,66.22 135.8,66.32 135.9,66.47 136.85,66.64 173.31,60.21 173.34,60.2 173.37,60.19 173.82,60.11 178.14,57.1 211.59,51.13 214.13,49.35 215.14,47.91 215.12,47.78 215.51,47.22 215.64,47.19 216.35,46.18 216.5,45.35 216.24,43.84 216.46,42.55 217.58,40.95 217.68,40.41 217.68,39.48 218.16,38.79 218.41,38.62 218.54,38.43 218.68,37.64 218.68,34.66 218.54,34.52 218.4,34.44 218.2,34.51 J2.A77
  BOTTOM w0.135: v3(58.45,69.56) 58.85,69.96 U1.U5
PE_SLOT2_RX_DN<15>: length 186.2
  IN2 w0.089: 57.37,66.14 57.37,66.17 57.42,66.21 57.42,66.9 57.28,67.04 57.28,68.99 v3(57.65,69.56)
  IN2 w0.145: J2.A81 214.2,34.51 214.4,34.44 214.54,34.52 214.68,34.66 214.68,38.06 213.79,39.33 213.67,40.03 213.67,40.72 212.84,45.41 210.65,48.54 209.84,49.11 209.68,49.08 209.29,49.35 209.26,49.51 208.59,49.98 208.43,49.95 208.04,50.22 208.02,50.38 207.47,50.77 177.62,56.03 172.96,59.29 137.57,65.54 86.75,56.51 86.11,56.62 81.23,55.76 80.95,55.48 76.79,54.74 71.42,54.74 70.94,55.22 70.61,55.22 70.13,54.74 69.56,54.74 69.08,55.22 68.74,55.22 68.26,54.74 67.69,54.74 67.21,55.22 66.88,55.22 66.4,54.74 64.42,54.74 57.37,61.78 57.37,66.14
  BOTTOM w0.135: v3(57.65,69.56) 58.05,69.96 U1.V5
PE_SLOT2_RX_DP<0>: length 229.5
  IN2 w0.089: 74.39,75.92 74.37,75.92 74.33,75.87 73.46,75.87 72.33,74.74 69.39,74.74 v3(68.85,74.36)
  IN2 w0.145: J2.A16 278.46,34 278.52,34.2 278.7,34.29 278.97,34.55 278.97,38.23 277.93,39.27 277.93,40.74 277.57,41.25 276.31,43.04 276.01,44.74 274.93,46.29 255.86,59.64 184.21,72.27 180.93,74.57 137.84,82.17 96.66,74.91 90.72,75.96 86.92,75.29 83,75.29 79.41,75.92 74.39,75.92
  BOTTOM w0.135: U1.E11 v3(68.85,74.36)
PE_SLOT2_RX_DP<1>: length 228.5
  IN2 w0.089: v3(68.85,73.56) 69.39,73.94 69.9,73.94 70.11,74.14 70.97,74.14 71.25,73.86 74.38,73.86 74.43,73.91 74.45,73.91
  IN2 w0.145: 74.45,73.91 74.77,73.91 75.05,73.96 77.54,74.99 78.05,75.08 80.13,74.71 80.41,74.3 80.39,74.15 80.54,73.92 80.81,73.88 81.03,74.03 81.06,74.19 81.47,74.48 83.01,74.2 87.28,74.2 90.63,74.79 96.77,73.71 118.22,77.49 118.22,77.5 137.86,80.96 180.54,73.43 183.89,71.09 254.13,58.71 268.04,48.97 268.13,48.48 267.51,47.6 267.56,47.33 267.78,47.17 268.05,47.22 268.67,48.1 269.16,48.19 270.58,47.2 272.09,45.03 272.59,42.19 273.97,40.23 273.97,39.22 272.97,38.22 272.97,34.67 273.12,34.52 273.26,34.44 273.46,34.51 J2.A21
  BOTTOM w0.135: U1.E10 v3(68.85,73.56)
PE_SLOT2_RX_DP<2>: length 220.6
  IN2 w0.089: v3(68.85,71.96) 69.39,72.34 74.38,72.34 74.43,72.38 74.45,72.38
  IN2 w0.145: J2.A25 269.46,34.51 269.26,34.44 269.26,34.45 269.12,34.52 268.97,34.67 268.97,38.15 269.95,39.14 269.95,40.76 267.97,43.58 267.7,45.11 265.13,48.78 252.1,57.9 183.58,69.99 180.02,72.48 137.99,79.89 96.6,72.59 90.85,73.6 87.13,72.95 78.11,72.95 74.92,72.38 74.45,72.38
  BOTTOM w0.135: U1.E8 v3(68.85,71.96)
PE_SLOT2_RX_DP<3>: length 220.1
  IN2 w0.089: v3(68.85,71.16) 69.39,71.54 69.9,71.54 70.11,71.74 71.99,71.74 71.99,71.74 73.9,71.4 74.38,71.4 74.43,71.45 74.45,71.45
  IN2 w0.145: 74.45,71.45 75.28,71.45 78.25,71.97 87.59,71.97 90.96,72.57 96.52,71.59 137.7,78.85 179.19,71.53 182.94,68.91 240.97,58.68 250.77,56.95 258.85,51.29 259.49,50.38 259.41,49.88 258.52,49.26 258.47,48.99 258.62,48.77 258.89,48.72 259.78,49.35 260.28,49.26 260.56,48.85 260.48,48.35 259.95,47.98 259.91,47.78 260.12,47.48 260.32,47.45 260.85,47.82 261.35,47.73 262.1,46.65 262.82,45.63 262.84,45.57 263.41,42.31 263.7,41.89 263.98,40.34 263.98,39.25 264.97,38.26 264.97,34.67 265.12,34.52 265.26,34.44 265.46,34.51 J2.A29
  BOTTOM w0.135: U1.E7 v3(68.85,71.16)
PE_SLOT2_RX_DP<4>: length 211.2
  IN2 w0.089: v3(68.85,69.56) 69.39,69.94 72.03,69.94 72.86,70.08 74.04,70.08 74.08,70.13 74.1,70.13
  IN2 w0.145: 74.1,70.13 74.65,70.13 78.05,70.73 87.16,70.73 90.46,71.31 95.84,70.36 137.66,77.74 178.6,70.52 182.51,67.79 236.29,58.3 248.01,56.23 252.28,53.24 257.49,45.81 257.87,43.63 258.4,42.88 258.64,42.64 259.88,40.88 259.88,40.88 259.97,40.33 259.97,39.24 258.97,38.24 258.97,34.67 259.12,34.52 259.26,34.44 259.46,34.51 J2.A35
  BOTTOM w0.135: U1.E5 v3(68.85,69.56)
PE_SLOT2_RX_DP<5>: length 209.4
  IN2 w0.089: v3(68.85,68.76) 69.39,69.14 69.9,69.14 70.11,69.34 73.1,69.34 73.38,69.06 73.77,69.06 73.82,69.11 73.84,69.11
  IN2 w0.145: J2.A39 255.46,34.51 255.26,34.44 255.12,34.52 254.97,34.67 254.97,38.25 255.96,39.24 255.96,40.15 255.85,40.76 255.05,41.59 254.03,43.05 253.27,47.37 249.74,52.4 245.15,55.62 181.88,66.77 177.97,69.51 137.24,76.69 93.5,68.97 93.02,69.06 92.87,69.28 92.91,69.53 92.62,69.94 92.13,70.03 91.72,69.74 91.67,69.49 91.45,69.34 91.18,69.38 91.03,69.6 91.07,69.85 90.79,70.26 90.29,70.35 89.88,70.06 89.84,69.82 89.65,69.68 78.24,69.68 74.96,69.11 73.84,69.11
  BOTTOM w0.135: U1.E4 v3(68.85,68.76)
PE_SLOT2_RX_DP<6>: length 202.7
  IN2 w0.089: v3(68.85,67.16) 69.39,67.54 69.9,67.54 70.11,67.74 70.97,67.74 71.25,67.46 72.22,67.46 72.26,67.51 72.29,67.51
  IN2 w0.145: 72.29,67.51 72.56,67.51 74.45,67.84 78.73,68.6 89.45,68.6 93.29,67.92 136.97,75.62 177.49,68.48 181.52,65.65 228.66,57.34 240.8,55.2 245.15,52.15 249.86,45.42 250.32,42.84 251.82,40.69 251.94,39.97 251.94,39.19 250.97,38.21 250.97,34.67 251.12,34.52 251.26,34.44 251.46,34.51 J2.A43
  BOTTOM w0.135: U1.E2 v3(68.85,67.16)
PE_SLOT2_RX_DP<7>: length 200.7
  IN2 w0.089: v3(68.85,66.36) 69.39,66.74 71.86,66.74 71.91,66.78 71.93,66.78
  IN2 w0.145: 71.93,66.78 73.52,66.78 73.55,66.79 74.45,66.95 77.66,67.53 78.39,67.53 78.63,67.28 79.29,67.28 79.53,67.53 80.34,67.53 80.59,67.28 81.24,67.28 81.49,67.53 82.86,67.53 85.23,67.11 85.46,67.26 85.5,67.53 85.86,67.78 86.45,67.67 86.7,67.31 86.65,67.05 86.81,66.83 87.91,66.63 88.13,66.79 88.23,67.31 88.64,67.6 89.13,67.51 89.42,67.1 89.33,66.58 89.48,66.36 90.31,66.21 136.72,74.4 177.37,67.23 181.11,64.61 238.11,54.56 241.73,52.03 242.42,51.05 243.51,44.84 245.89,41.45 245.98,40.94 245.98,39.22 246.97,38.23 246.97,34.67 247.12,34.52 247.26,34.44 247.46,34.51 J2.A47
  BOTTOM w0.135: U1.E1 v3(68.85,66.36)
PE_SLOT2_RX_DP<8>: length 197.4
  IN2 w0.089: 66.87,65.89 66.87,65.91 66.83,65.95 66.83,68.99 v3(66.45,69.56)
  IN2 w0.145: 66.87,65.89 66.87,65.54 67.11,65.3 70.69,65.3 71.3,65.91 74.18,65.91 74.45,65.96 76.14,66.26 83.35,66.26 90.24,65.04 136.7,73.23 177.1,66.11 180.8,63.52 225.33,55.67 237.76,46.96 241.97,40.95 241.97,39.36 242.95,38.38 242.95,34.54 242.7,34.29 242.52,34.2 242.46,34 J2.A52
  BOTTOM w0.135: U1.H5 v3(66.45,69.56)
PE_SLOT2_RX_DP<9>: length 196.1
  IN2 w0.089: 65.84,66.89 65.85,66.9 65.85,66.97 66.27,67.38 66.27,68.21 66.03,68.45 66.03,68.99 v3(65.65,69.56)
  IN2 w0.145: 65.84,66.89 65.6,66.65 65.6,65.54 66.63,64.52 72.09,64.52 72.72,65.15 75.73,65.15 76.06,64.82 76.67,64.82 77,65.15 77.85,65.15 78.17,64.82 78.79,64.82 79.11,65.15 79.96,65.15 80.29,64.82 80.9,64.82 81.23,65.15 83.2,65.15 89.77,63.99 136.42,72.22 176.29,65.19 180.06,62.55 223.46,54.89 231.22,49.46 233.68,47 235.41,44.53 237.99,40.55 237.99,39.36 238.97,38.38 238.97,34.55 238.7,34.29 238.52,34.2 238.51,34.19 238.45,34.01 J2.A56
  BOTTOM w0.135: U1.J5 v3(65.65,69.56)
PE_SLOT2_RX_DP<10>: length 194.3
  IN2 w0.089: 63.9,65.84 63.9,65.86 63.85,65.91 63.85,66.57 64.43,67.15 64.43,68.99 v3(64.05,69.56)
  IN2 w0.145: J2.A60 234.49,33.94 234.58,34.23 234.7,34.29 234.98,34.56 234.98,38.4 234.01,39.37 234.01,40.31 233.88,41.08 227.8,49.76 221.24,54.36 179.34,61.74 175.91,64.15 136.49,71.1 88.09,62.57 84.6,63.67 78.44,63.67 77.97,63.2 77.29,63.2 76.73,63.75 75.75,63.75 75.19,63.2 74.21,63.2 73.66,63.75 65.14,63.75 63.9,65 63.9,65.84
  BOTTOM w0.135: U1.L5 v3(64.05,69.56)
PE_SLOT2_RX_DP<11>: length 193.2
  IN2 w0.089: v3(63.25,69.56) 63.63,68.99 63.63,68.45 63.91,68.17 63.91,67.72 63.03,66.84 63.03,66.01 63.07,65.96 63.07,65.94
  IN2 w0.145: 63.07,65.94 63.07,64.13 63.83,63.37 63.83,63.12 65.84,61.11 77.29,61.11 77.7,61.52 78.54,61.52 78.94,61.11 79.86,61.11 80.22,61.18 80.42,61.47 81.29,61.62 81.58,61.42 82.15,61.52 82.35,61.81 83.22,61.96 83.51,61.76 84.28,61.89 85.85,61.61 86.86,61.44 136.27,70.15 175.55,63.24 178.94,60.87 219.53,53.71 222.39,51.89 229.74,41.4 229.97,40.06 229.97,39.35 230.96,38.35 230.96,34.55 230.7,34.29 230.51,34.19 230.45,34.01 J2.A64
  BOTTOM w0.135: U1.M5 62.85,69.96 v3(63.25,69.56)
PE_SLOT2_RX_DP<12>: length 191.8
  IN2 w0.089: v3(60.85,69.56) 61.23,68.99 61.23,67.32 61.47,67.08 61.47,66.5 61.51,66.45 61.51,66.43
  IN2 w0.145: J2.A68 226.46,34 226.52,34.2 226.7,34.29 226.96,34.55 226.96,38.35 225.97,39.35 225.97,40.44 225.8,41.38 224.77,42.86 224.27,45.66 220.21,51.47 218.28,52.82 178.84,59.77 175.39,62.19 136.27,69.09 86.37,60.3 84.19,60.68 78.06,59.6 77.3,59.07 76.48,58.93 65.61,58.93 62.12,62.42 62.12,64.07 61.51,64.67 61.51,66.43
  BOTTOM w0.135: U1.P5 v3(60.85,69.56)
PE_SLOT2_RX_DP<13>: length 189.8
  IN2 w0.089: v3(60.05,69.56) 60.43,68.99 60.43,66.8 60.47,66.76 60.47,66.73
  IN2 w0.145: J2.A72 222.46,34 222.52,34.2 222.7,34.29 222.96,34.55 222.96,38.13 222.75,38.53 222.26,38.94 222.04,39.16 221.97,39.55 221.97,40.26 221.7,41.79 220.66,43.27 219.72,48.59 217.86,51.26 217.11,51.78 178.32,58.62 174.46,61.32 137.18,67.89 136.68,67.98 87.13,59.24 86.06,59.05 83.73,59.47 78.49,58.54 77.66,58.2 76.75,58.04 65.1,58.04 60.47,62.67 60.47,66.73
  BOTTOM w0.135: v3(60.05,69.56) 60.45,69.96 U1.R5
PE_SLOT2_RX_DP<14>: length 188.3
  IN2 w0.089: 58.8,66.56 58.8,66.59 58.75,66.64 58.75,66.91 58.05,67.61 58.05,68.12 58.27,68.34 58.27,68.58 v3(58.45,68.76)
  IN2 w0.145: J2.A76 218.46,34 218.52,34.2 218.7,34.29 218.96,34.55 218.96,37.67 218.81,38.54 218.61,38.82 218.36,38.99 217.96,39.57 217.96,40.43 217.85,41.06 216.73,42.66 216.62,43.25 216.52,43.84 216.78,45.35 216.62,46.29 214.34,49.55 211.7,51.4 178.25,57.36 173.93,60.38 173.45,60.46 173.38,60.48 173.36,60.48 136.85,66.92 85.63,57.84 85.19,58.15 84.53,58.03 84.3,57.7 81.2,57.15 80.47,57.15 80.02,57.6 79.42,57.6 78.97,57.15 73.83,57.15 73.39,56.71 73.01,56.71 72.58,57.15 64.11,57.15 62.74,58.52 62.74,58.7 62.27,59.17 62.09,59.17 61.8,59.46 61.8,59.68 61.37,60.11 61.15,60.11 60.89,60.36 60.89,60.56 60.44,61.02 60.24,61.02 59.82,61.43 59.82,61.62 59.35,62.09 59.17,62.09 58.8,62.46 58.8,63.64 58.92,63.76 58.92,64.27 58.8,64.39 58.8,64.84 58.92,64.96 58.92,65.47 58.8,65.59 58.8,66.56
  BOTTOM w0.135: U1.U4 v3(58.45,68.76)
PE_SLOT2_RX_DP<15>: length 186.1
  IN2 w0.089: v3(57.65,68.76) 57.47,68.58 57.47,67.12 57.61,66.98 57.61,66.21 57.65,66.17 57.65,66.14
  IN2 w0.145: 57.65,66.14 57.65,61.9 58.08,61.47 58.25,61.47 58.62,61.1 58.62,60.93 58.99,60.56 59.16,60.56 59.53,60.2 59.53,60.03 60.06,59.49 60.23,59.49 60.6,59.12 60.6,58.96 60.97,58.58 61.14,58.58 61.51,58.22 61.51,58.05 61.91,57.64 62.08,57.64 62.45,57.27 62.45,57.11 62.82,56.73 62.99,56.73 63.35,56.37 63.35,56.2 64.53,55.02 66.28,55.02 66.76,55.5 67.33,55.5 67.81,55.02 68.15,55.02 68.63,55.5 69.19,55.5 69.67,55.02 70.01,55.02 70.49,55.5 71.06,55.5 71.54,55.02 76.76,55.02 80.81,55.74 81.1,56.02 86.11,56.91 86.75,56.79 137.57,65.82 173.07,59.56 177.73,56.3 207.58,51.03 210.84,48.75 213.1,45.52 213.95,40.74 213.95,40.06 214.05,39.44 214.96,38.14 214.96,34.55 214.7,34.29 214.52,34.2 214.46,34 J2.A80
  BOTTOM w0.135: U1.V4 v3(57.65,68.76)
PE_SLOT2_TX_C_DN<0>: length 219.1
  BOTTOM w0.135: U1.A11 71.75,74.67 72.48,74.67 72.62,74.8 73.07,74.8 73.2,74.67 73.76,74.67 74.2,75.11 78.34,75.11 78.56,74.88 79.56,74.88 79.74,75.06 80.28,75.06 80.45,74.88 80.99,74.88 81.17,75.06 81.71,75.06 81.89,74.88 82.77,74.88 125.88,82.48 v6(128.99,81.93) 131.06,81.57 132.48,81.31 132.56,81.3 260.94,58.54 268.01,53.59 268.95,52.93 268.95,52.93 274.21,49.25 278.44,48.5 281.14,46.62 281.47,46.24 281.92,45.6 281.92,44.82 C31.1
PE_SLOT2_TX_C_DN<1>: length 217.6
  BOTTOM w0.135: C32.1 273.96,44.82 273.96,45.53 273.72,46.86 273.09,47.75 270.02,49.9 269.51,49.81 268.99,49.07 268.73,49.02 268.51,49.18 268.47,49.44 268.99,50.18 268.9,50.69 268.47,50.99 267.93,50.89 267.52,50.31 267.25,50.26 267.04,50.42 267,50.64 267.43,51.27 267.34,51.78 266.92,52.08 266.41,51.99 265.98,51.37 265.7,51.32 265.48,51.48 265.44,51.73 265.88,52.36 265.79,52.87 262.41,55.23 261.42,55.93 259.84,57.03 125.35,80.91 v6(122.66,80.43) 88.14,74.35 87.98,74.46 87.45,74.37 87.34,74.21 86.81,74.11 86.65,74.22 86.12,74.13 86.01,73.97 85.48,73.88 85.32,73.99 84.79,73.9 84.68,73.74 83.86,73.59 82.61,73.59 82.55,73.66 81.85,73.66 81.79,73.59 81.08,73.59 81.01,73.66 80.32,73.66 80.25,73.59 79.71,73.59 79.64,73.66 78.95,73.66 78.88,73.59 77.06,73.59 76.79,73.87 71.75,73.87 U1.A10
PE_SLOT2_TX_C_DN<2>: length 206.6
  BOTTOM w0.135: U1.A8 71.75,72.27 73.11,72.27 73.51,72.67 76.28,72.67 76.71,72.24 77.53,72.24 77.68,72.39 78.22,72.39 78.37,72.24 78.91,72.24 79.06,72.39 79.6,72.39 79.75,72.24 80.29,72.24 80.44,72.39 80.98,72.39 81.13,72.24 84.07,72.24 125.33,79.51 v6(127.35,79.16) 128.87,78.89 254.85,56.56 260.98,52.27 260.98,52.27 261.98,51.57 269.27,46.46 269.56,46.17 269.96,45.6 269.96,44.82 C33.1
PE_SLOT2_TX_C_DN<3>: length 204.7
  BOTTOM w0.135: C34.1 265.96,44.82 265.96,45.53 265.93,45.68 265.9,45.86 265.64,46.23 263.46,47.76 262.95,47.67 262.73,47.35 262.46,47.3 262.24,47.45 262.2,47.72 262.42,48.03 262.33,48.55 261.91,48.84 261.4,48.75 261.17,48.43 260.91,48.39 260.69,48.54 260.64,48.83 260.86,49.15 260.78,49.63 254.31,54.16 251.94,55.82 126.44,78.1 124.68,77.79 v6(123.38,77.56) 85.42,70.87 80.79,70.87 80.64,71.02 80.1,71.02 79.95,70.87 79.41,70.87 79.25,71.02 78.72,71.02 78.56,70.87 78.03,70.87 77.87,71.02 77.33,71.02 77.18,70.87 75.99,70.87 75.39,71.46 73.27,71.46 73.26,71.47 71.75,71.47 U1.A7
PE_SLOT2_TX_C_DN<4>: length 196.3
  BOTTOM w0.135: U1.A5 71.75,69.87 72.38,69.87 72.78,70.26 74.49,70.26 75.29,69.47 76.43,69.47 76.58,69.62 77.12,69.62 77.27,69.47 77.81,69.47 77.96,69.62 78.5,69.62 78.65,69.47 79.19,69.47 79.34,69.62 79.88,69.62 80.04,69.47 84.49,69.47 v6(121.81,76.05) 126.43,76.87 246.1,55.64 259.5,46.25 259.81,45.81 259.96,45.6 259.96,44.82 C67.1
PE_SLOT2_TX_C_DN<5>: length 194
  BOTTOM w0.135: U1.A4 71.75,69.07 73.05,69.07 73.05,69.06 73.97,69.06 74.93,68.1 76.06,68.1 76.21,68.25 76.75,68.25 76.91,68.1 77.44,68.1 77.6,68.25 78.13,68.25 78.29,68.1 78.83,68.1 78.98,68.25 79.52,68.25 79.67,68.1 83.83,68.1 v6(125.04,75.36) 126.53,75.63 243.39,54.89 246.33,52.83 246.33,52.83 249.19,50.83 249.55,50.89 249.63,51 250.24,51.11 250.75,50.75 250.86,50.13 250.64,49.81 250.7,49.46 251.01,49.25 251.38,49.31 251.6,49.62 252.21,49.73 254.58,48.07 255.09,47.33 255.96,45.25 255.96,44.82 C68.1
PE_SLOT2_TX_C_DN<6>: length 187.9
  BOTTOM w0.135: C69.1 251.96,44.82 251.96,45.53 251.87,46.01 251.83,46.08 251.42,46.66 250.98,47.29 241.64,53.83 241.39,54 126.26,74.3 v6(121.7,73.5) 83.15,66.7 79.65,66.7 79.49,66.85 78.96,66.85 78.8,66.7 78.26,66.7 78.11,66.85 77.57,66.85 77.42,66.7 76.88,66.7 76.73,66.85 76.19,66.85 76.04,66.7 74.6,66.7 74.22,67.08 73.11,67.08 72.72,67.47 71.75,67.47 U1.A2
PE_SLOT2_TX_C_DN<7>: length 186.4
  BOTTOM w0.135: C70.1 247.96,44.82 247.96,47.07 247.59,47.64 247.24,48.17 245.64,49.29 245.13,49.2 245.01,49.04 244.75,48.99 244.53,49.14 244.48,49.41 244.6,49.57 244.51,50.08 244.08,50.38 243.57,50.29 243.46,50.12 243.2,50.08 242.98,50.23 242.93,50.49 243.05,50.66 242.96,51.17 240.65,52.78 126.89,72.97 v6(118.78,71.54) 84.27,65.46 74.47,65.46 73.86,66.07 71.65,66.07 71.41,66.31 71.41,66.52 U1.A1
PE_SLOT2_TX_C_DN<8>: length 188.5
  BOTTOM w0.135: C71.1 245.92,44.82 245.92,45.48 245.4,46.25 237.15,52.03 126.77,71.5 v6(123.52,70.93) 84.71,64.08 78.79,64.08 78.64,64.24 78.1,64.24 77.94,64.08 77.41,64.08 77.25,64.24 76.72,64.24 76.56,64.08 76.02,64.08 75.87,64.24 75.33,64.24 75.18,64.08 74.6,64.08 73.53,65.15 72.42,65.15 71.86,64.59 70.54,64.59 70.39,64.74 69.85,64.74 69.7,64.59 69.16,64.59 69.01,64.74 68.47,64.74 68.32,64.59 67.69,64.59 67.39,64.9 67.39,65.1 67.18,65.3 66.98,65.3 66.63,65.66 66.63,65.91 66.45,66.09 66.19,66.09 65.96,66.32 65.96,66.67 U1.H1
PE_SLOT2_TX_C_DN<9>: length 187.5
  BOTTOM w0.135: C72.1 241.94,44.82 241.94,45.53 241.7,46.86 241.2,47.57 239.73,48.6 239.22,48.51 239.03,48.25 238.77,48.2 238.55,48.35 238.51,48.62 238.69,48.88 238.6,49.39 236.72,50.71 229.74,51.94 229.74,51.94 222.33,53.25 221.16,53.46 221.15,53.46 211.78,55.11 211.78,55.11 210.62,55.32 210.62,55.31 201.72,56.89 201.72,56.88 126.88,70.09 v6(119.02,68.7) 87.53,63.15 87.42,63.23 86.8,63.12 86.72,63.01 86.19,62.91 86.08,62.99 85.46,62.88 85.38,62.77 84.63,62.64 77.43,62.64 77.28,62.79 76.74,62.79 76.59,62.64 76.05,62.64 75.9,62.79 75.36,62.79 75.21,62.64 74.12,62.64 73.82,62.93 73.82,63.14 73.44,63.52 73.24,63.52 72.98,63.78 71.12,63.78 70.97,63.93 70.43,63.93 70.28,63.78 69.74,63.78 69.59,63.93 69.05,63.93 68.9,63.78 66.76,63.78 66.6,63.94 66.6,64.11 66.4,64.31 66.22,64.31 66.07,64.47 66.07,64.64 65.86,64.85 65.69,64.85 65.53,65 65.53,65.48 65.16,65.85 65.16,66.67 U1.J1
PE_SLOT2_TX_C_DN<10>: length 185
  BOTTOM w0.135: C73.1 237.97,44.82 237.97,45.6 237.84,46.38 232.55,50.08 229.74,50.58 228.59,50.78 228.59,50.78 222.17,51.91 211.56,53.78 211.56,53.78 210.41,53.99 127.18,68.65 v6(123.91,68.08) 84.99,61.21 74.77,61.21 74.62,61.37 74.08,61.37 73.93,61.21 73.39,61.21 73.24,61.37 72.7,61.37 72.55,61.21 69.58,61.21 69.4,61.39 68.87,61.39 68.69,61.21 68.24,61.21 68.09,61.37 67.55,61.37 67.4,61.21 66.86,61.21 66.7,61.37 66.17,61.37 66.01,61.21 65.74,61.21 65.05,61.9 65.05,62.65 65.18,62.78 65.18,63.42 65.05,63.55 65.05,64.08 64.77,64.36 64.77,64.57 64.53,64.81 64.33,64.81 63.56,65.57 63.56,66.67 U1.L1
PE_SLOT2_TX_C_DN<11>: length 183.4
  BOTTOM w0.135: C74.1 234.01,44.82 234.01,45.53 233.95,45.89 232.82,47.5 230.81,48.9 222.67,50.35 222.67,50.35 221.5,50.56 221.5,50.56 211.34,52.36 211.34,52.36 200.33,54.31 200.32,54.31 199.19,54.52 199.18,54.52 126.86,67.35 v6(119.33,66.02) 80.83,59.23 80.51,59.23 80.35,59.39 79.82,59.39 79.66,59.23 79.12,59.23 78.97,59.39 78.43,59.39 78.28,59.23 77.74,59.23 77.59,59.39 77.05,59.39 76.9,59.23 73.54,59.23 73.38,59.39 72.85,59.39 72.69,59.23 69.47,59.23 69.31,59.39 68.78,59.39 68.62,59.23 66.83,59.23 66.73,59.33 66.27,59.33 66.17,59.23 65.61,59.23 64.78,60.07 64.78,60.22 64.29,60.7 64.14,60.7 63.7,61.14 63.7,61.72 63.81,61.83 63.81,62.33 63.7,62.43 63.7,62.71 63.81,62.81 63.81,63.3 63.7,63.4 63.7,63.73 63.38,64.06 63.38,64.21 63.15,64.44 62.99,64.44 62.76,64.67 62.76,65.13 62.87,65.23 62.87,65.53 62.76,65.63 62.76,66.67 U1.M1
PE_SLOT2_TX_C_DN<12>: length 181.2
  BOTTOM w0.135: C75.1 229.97,44.82 229.97,46.32 227.56,48.01 126.46,65.84 v6(123.29,65.28) 81.08,57.84 68.96,57.84 68.81,57.99 68.27,57.99 68.12,57.84 67.58,57.84 67.43,57.99 66.89,57.99 66.74,57.84 65.03,57.84 64.24,58.62 64.24,58.87 63.86,59.25 63.61,59.25 63.23,59.63 63.23,59.89 62.85,60.27 62.59,60.27 62.08,60.78 62.08,61.59 62.23,61.74 62.23,62.33 62.08,62.48 62.08,63.83 61.84,64.07 61.84,64.25 61.61,64.48 61.43,64.48 61.16,64.75 61.16,65.18 61.27,65.28 61.27,65.79 61.16,65.89 61.16,66.67 U1.P1
PE_SLOT2_TX_C_DN<13>: length 180.8
  BOTTOM w0.135: U1.R1 60.36,66.67 60.36,63.95 60.58,63.73 60.58,62.76 60.73,62.61 60.73,62.2 60.58,62.05 60.58,61.47 60.68,61.37 60.68,60.88 60.58,60.78 60.58,60.35 61.44,59.49 61.67,59.49 62.05,59.11 62.05,58.88 62.43,58.5 62.66,58.5 63.04,58.12 63.04,57.89 63.42,57.51 63.65,57.51 64.03,57.13 64.03,56.9 66.02,54.91 66.8,54.91 66.95,55.07 67.49,55.07 67.64,54.91 68.18,54.91 68.33,55.07 68.87,55.07 69.02,54.91 70.44,54.91 72.11,53.24 76.89,53.24 77.58,53.36 82.28,56.65 v6(119.83,63.27) 126.73,64.49 222.48,47.6 225.46,46.13 225.84,45.79 225.84,45.79 225.94,45.69 226.04,45.48 226.04,44.82 C76.1
PE_SLOT2_TX_C_DN<14>: length 180.3
  BOTTOM w0.135: C77.1 222.06,44.8 222.06,45.34 221.47,45.93 220.38,46.7 126.99,63.17 v6(123.09,62.48) 95.38,57.59 87.67,52.19 87.51,52.22 86.96,51.83 86.93,51.67 86.21,51.17 85.5,50.67 83.31,50.31 81.26,50.67 79.6,51.83 74.96,51.83 74.82,51.97 74.29,51.97 74.15,51.83 73.61,51.83 73.48,51.97 72.94,51.97 72.8,51.83 71.82,51.83 70.36,53.29 65.69,53.29 62.56,56.42 62.56,56.59 62.1,57.05 61.92,57.05 61.54,57.43 61.54,57.61 61.09,58.07 60.91,58.07 60.53,58.45 60.53,58.63 60.07,59.08 59.89,59.08 59.26,59.72 59.26,60.4 59.36,60.5 59.36,60.91 59.26,61.01 59.26,61.44 59.36,61.54 59.36,61.9 59.26,62 59.26,62.48 59.09,62.66 59.09,64.47 59.18,64.57 59.18,65.28 58.76,65.7 58.76,66.67 U1.U1
